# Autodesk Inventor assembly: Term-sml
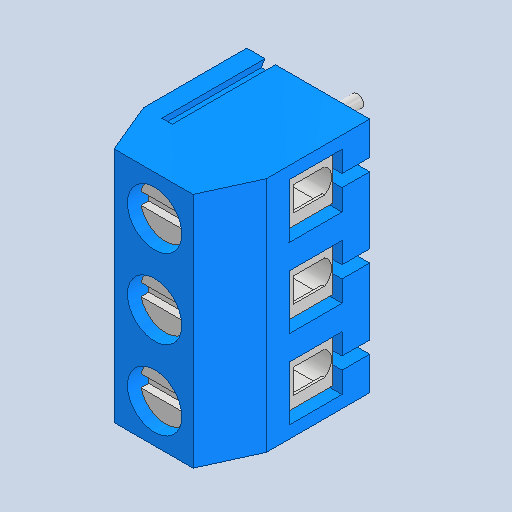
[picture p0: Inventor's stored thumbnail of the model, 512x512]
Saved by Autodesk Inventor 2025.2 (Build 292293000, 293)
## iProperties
Created: 2025-04
Part Number: Term-sml
Description: PART--DESC
Document SubType Name: Assembly
Designer: BennF
Author: BennF
Revision Number: NONE
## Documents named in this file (3)
- C:\Users\BennF\Nextcloud\Benutzer\CNC JarBeRi\existing parts\Electronics\RepRap A4988 Shied (USE WITHOUT ARDUINO)\reprap-a4988-1.snapshot.1\RepRap\RepRap\Term-sml_1.iam
- C:\Users\BennF\Nextcloud\Benutzer\CNC JarBeRi\existing parts\Electronics\RepRap A4988 Shied (USE WITHOUT ARDUINO)\reprap-a4988-1.snapshot.1\RepRap\RepRap\Term-sml Geometry.ipt
- C:\Users\BennF\Nextcloud\Benutzer\CNC JarBeRi\existing parts\Electronics\RepRap A4988 Shied (USE WITHOUT ARDUINO)\reprap-a4988-1.snapshot.1\RepRap\RepRap\pins.ipt
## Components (2 placed, 2 different names)
1. Term-sml Geometry
2. pins
